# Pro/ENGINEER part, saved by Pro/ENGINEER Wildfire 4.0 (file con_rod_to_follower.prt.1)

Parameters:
  METRIC = "NO"

Other parameters: PITCH, DRILL_POINT_ANGLE, DRILL_DEPTH, DRILL_DIAMETER, THREAD_DIAMETER, THREADS_PER_INCH, THREAD_DEPTH, THREAD_LENGTH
